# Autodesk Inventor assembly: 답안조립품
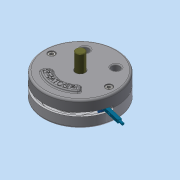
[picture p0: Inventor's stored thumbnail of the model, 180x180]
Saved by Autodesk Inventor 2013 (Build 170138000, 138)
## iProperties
Created: 2015-04
Part Number: 답안조립품
Document SubType Name: Assembly
Designer: Administrator
Author: Administrator
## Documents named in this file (10)
- C:\Users\Administrator\Desktop\450406V1010\답안조립품.iam
- C:\Users\Administrator\Desktop\450406V1010\본체.ipt
- C:\Users\Administrator\Desktop\450406V1010\M 10 x 35.ipt
- C:\Users\Administrator\Desktop\450406V1010\덮개.ipt
- C:\Users\Administrator\Desktop\450406V1010\멈춤링.ipt
- C:\Users\Administrator\Desktop\450406V1010\베어링62_22.ipt
- C:\Users\Administrator\Desktop\450406V1010\슬라이더.ipt
- C:\Users\Administrator\Desktop\450406V1010\슬라이더2.ipt
- C:\Users\Administrator\Desktop\450406V1010\축.ipt
- C:\Users\Administrator\Desktop\450406V1010\평행핀.ipt
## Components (2 placed, 1 different names)
1. M 10 x 35:1
2. M 10 x 35:2
